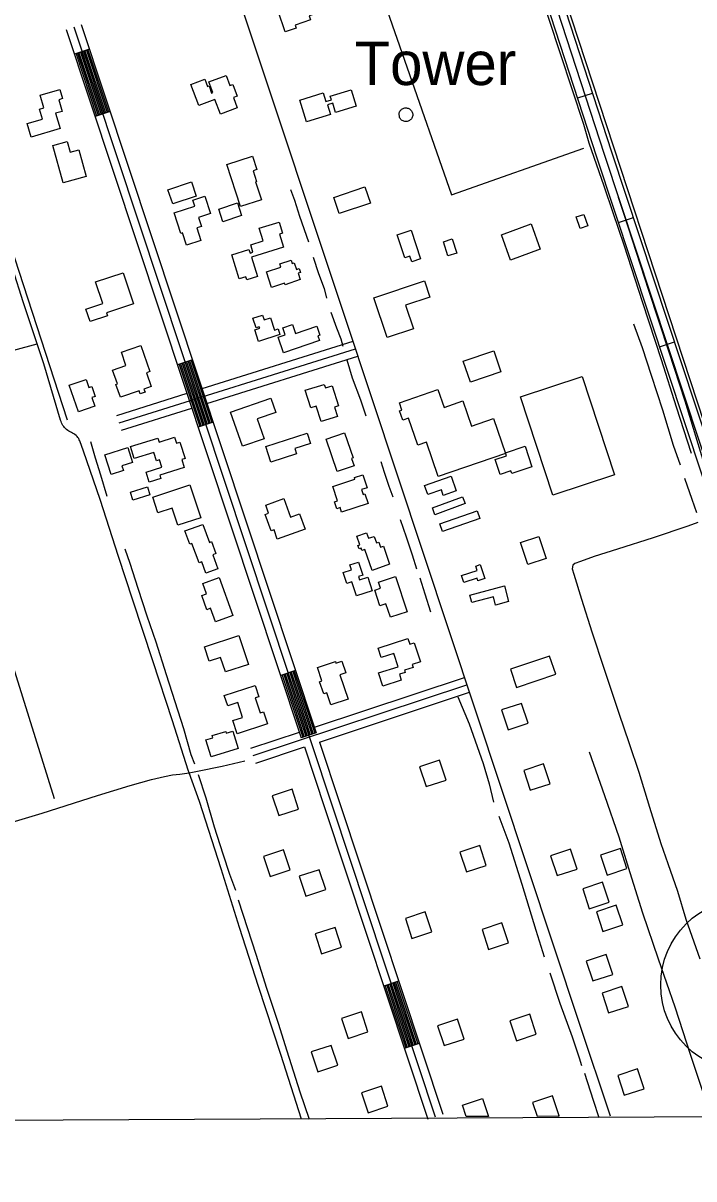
# Model space of a CAD drawing. Extents: x 3445503 to 3483459, y 540493 to 566012.
# Drawn here: x 3471547 to 3472827, y 545885 to 548092 of the extents above; entities that cross this region are included whole.
import ezdxf

# ---------------------------------------------------------------- set-up
doc = ezdxf.new("R2010")
doc.units = 0
for name, color, linetype in [('V-BLDG-OTLN', 7, 'Continuous'), ('V-DOMW-IDEN', 7, 'Continuous'), ('V-DOMW-TANK', 7, 'Continuous'), ('V-DTCH-CNTR', 7, 'Continuous'), ('V-GRID-FRAM', 7, 'Continuous'), ('V-ROAD-CNTR', 7, 'Continuous'), ('V-ROAD-IDEN', 7, 'Continuous'), ('V-TOPO-SHOR', 7, 'Continuous')]:
    doc.layers.add(name, color=color, linetype=linetype)

msp = doc.modelspace()

# ---------------------------------------------------------------- linework, layer by layer
at = {"layer": 'V-BLDG-OTLN'}
for p, q in [((3472434.9, 546004.5), (3472392.8, 546004.2)), ((3472528.1, 546004.9), (3472569.9, 546005.8)), ((3472569.9, 546005.8), (3472567.8, 546005.1))]:
    msp.add_line(p, q, dxfattribs=at)
for points in [[(3472033.6, 548115.4), (3472083, 548132.1), (3472085.1, 548125.8), (3472102.5, 548131.7), (3472109.3, 548111.7), (3472092.7, 548106.1), (3472095.3, 548098.3), (3472066.1, 548088.4), (3472067.9, 548082.9), (3472046.9, 548075.8)], [(3471923.6, 547918.7), (3471913.3, 547946.5), (3471882.3, 547935), (3471867.5, 547975.2), (3471894.2, 547985.1), (3471899.3, 547971.3), (3471901.9, 547972.3), (3471906.9, 547958.8), (3471909, 547959.6), (3471901.4, 547980.1), (3471934.7, 547992.5), (3471941.8, 547973.4), (3471947.2, 547975.4), (3471955.5, 547952.8), (3471948.5, 547950.2), (3471955.8, 547930.6)], [(3471579.6, 547954.7), (3471617.5, 547965.8), (3471622.6, 547948.2), (3471615.1, 547945.9), (3471621.6, 547923.8), (3471609.1, 547920.1), (3471617.7, 547890.8), (3471562.3, 547874.5), (3471554.7, 547900.3), (3471584.3, 547909), (3471578.6, 547928.2), (3471586.7, 547930.6)], [(3472075.2, 547945.4), (3472120, 547959), (3472124.8, 547942.9), (3472135.3, 547946.1), (3472133.3, 547952.9), (3472173.3, 547964.9), (3472182.7, 547933.9), (3472143.2, 547921.9), (3472137.9, 547939.4), (3472128, 547936.4), (3472133.6, 547917.6), (3472087.7, 547903.7)], [(3471623.5, 547787), (3471603.6, 547858.9), (3471631.2, 547866.5), (3471636.9, 547846), (3471653.5, 547850.6), (3471667.7, 547799.3)], [(3471961.7, 547741.9), (3471935.7, 547822.1), (3471984.8, 547838), (3471993, 547812.6), (3471986.1, 547810.4), (3471992.8, 547789.6), (3471990.7, 547788.9), (3472001.8, 547754.8)], [(3471823.6, 547773.7), (3471868.4, 547788.9), (3471877.5, 547762.1), (3471832.7, 547746.9)], [(3472209.8, 547748.5), (3472150.4, 547728.5), (3472140, 547759.4), (3472199.4, 547779.4)], [(3471835.5, 547729.8), (3471875.1, 547742.7), (3471871.3, 547754.5), (3471893.7, 547761.8), (3471904.5, 547728.7), (3471881.9, 547721.3), (3471887.5, 547704.2), (3471878.6, 547701.3), (3471886.5, 547677.2), (3471859.1, 547668.3), (3471851.6, 547691.6), (3471848.3, 547690.5)], [(3471920.4, 547736.9), (3471956.2, 547748.8), (3471964.1, 547725), (3471928.4, 547713.1)], [(3472617.1, 547727.1), (3472624.5, 547705.1), (3472609.8, 547700.3), (3472602.5, 547722.2)], [(3472044.2, 547664.4), (3471983.2, 547645.6), (3471994.7, 547608.3), (3471974, 547601.9), (3471972.1, 547608), (3471959.4, 547604), (3471945.3, 547649.6), (3471978.1, 547659.8), (3471980.2, 547653.1), (3471985.8, 547654.9), (3471981.5, 547669), (3472005.2, 547676.3), (3471997.7, 547700.6), (3472035.7, 547712.3), (3472042.3, 547691), (3472036.5, 547689.2)], [(3472459.7, 547688.1), (3472516.4, 547708.7), (3472534, 547660.4), (3472477.3, 547639.8)], [(3472287.5, 547696.9), (3472305.7, 547641.9), (3472288.7, 547636.3), (3472285.1, 547647.1), (3472275.2, 547643.8), (3472260.6, 547688)], [(3472366.1, 547680.2), (3472374.6, 547653.2), (3472357.6, 547647.8), (3472349, 547674.7)], [(3472011.4, 547617.1), (3472039.1, 547626.1), (3472037, 547632.7), (3472058.6, 547639.8), (3472060.7, 547633.3), (3472064.6, 547634.5), (3472068.8, 547621.8), (3472074.1, 547623.6), (3472076.6, 547616), (3472072.2, 547614.5), (3472076.1, 547602.4), (3472046.9, 547592.8), (3472046, 547595.4), (3472021.1, 547587.2)], [(3471738.1, 547615.6), (3471757.9, 547556.3), (3471706.5, 547539.2), (3471708.4, 547533.4), (3471674.9, 547522.3), (3471667, 547546.2), (3471699.2, 547557), (3471685.6, 547598.1)], [(3472216.3, 547567.9), (3472312.8, 547600.3), (3472323.3, 547569.1), (3472276.8, 547553.5), (3472291.9, 547508.6), (3472241.9, 547491.8)], [(3472019.3, 547529.6), (3472026.8, 547505.9), (3472033.9, 547508.2), (3472037.2, 547497.7), (3471996.3, 547484.6), (3471989.3, 547506.7), (3471998.6, 547509.7), (3471997.7, 547512.6), (3471991.7, 547510.7), (3471985.8, 547529.1), (3472004, 547534.9), (3472007, 547525.6)], [(3472044.2, 547462.4), (3472033.8, 547492.7), (3472047.1, 547497.2), (3472042.5, 547510.5), (3472061.2, 547516.9), (3472067.1, 547499.9), (3472107.5, 547513.8), (3472113.6, 547496.4), (3472109.7, 547495), (3472112.8, 547486)], [(3471771.6, 547476.8), (3471788.9, 547426.8), (3471782.6, 547424.6), (3471791.7, 547398.2), (3471777.8, 547393.4), (3471779.9, 547387.3), (3471770.5, 547384.1), (3471768.5, 547390.1), (3471732.7, 547377.8), (3471724.3, 547402.2), (3471727, 547403.2), (3471717.8, 547429.8), (3471743.4, 547438.7), (3471734.6, 547464)], [(3472387.1, 547446.7), (3472445.1, 547466.4), (3472458.6, 547426.6), (3472400.6, 547406.9)], [(3472613.8, 547417.4), (3472675.7, 547229.7), (3472558, 547190.9), (3472496.1, 547378.6)], [(3471652.6, 547349.9), (3471635.1, 547401), (3471667.2, 547412), (3471672.4, 547396.7), (3471678.2, 547398.7), (3471684.7, 547379.5), (3471678.5, 547377.4), (3471684.2, 547360.7)], [(3472115.8, 547331.5), (3472106.5, 547361.1), (3472095.9, 547357.8), (3472085.4, 547391.1), (3472121.9, 547402.5), (3472124, 547395.7), (3472137.1, 547399.8), (3472149.2, 547361.4), (3472141.5, 547359), (3472147.1, 547341.3)], [(3471965.6, 547284.4), (3471943, 547349.5), (3472019.8, 547376.1), (3472029.2, 547348.9), (3471993.7, 547336.6), (3472006.8, 547298.7)], [(3472265.1, 547367.5), (3472338.5, 547392.9), (3472350.4, 547358.4), (3472386, 547370.7), (3472402.6, 547322.6), (3472444.7, 547337.2), (3472467.7, 547270.7), (3472339.4, 547226.4), (3472316.8, 547292), (3472300.4, 547286.3), (3472282.6, 547337.8), (3472271.6, 547334), (3472265.4, 547352), (3472270, 547353.5)], [(3472010, 547283.8), (3472089.3, 547309.3), (3472095.7, 547289.6), (3472065.7, 547280), (3472069, 547269.5), (3472019.6, 547253.7)], [(3472146.6, 547235.9), (3472125.6, 547298), (3472160.7, 547309.9), (3472176.9, 547261.9), (3472173.8, 547260.9), (3472178.6, 547246.7)], [(3471854.7, 547243.4), (3471808, 547228.8), (3471809.9, 547222.8), (3471788, 547215.9), (3471782.1, 547235), (3471811.9, 547244.3), (3471807.5, 547258.2), (3471801.5, 547256.3), (3471796.4, 547272.6), (3471759.2, 547260.9), (3471752.2, 547283.5), (3471804.1, 547299.8), (3471806.5, 547292.3), (3471836.2, 547301.6), (3471839.8, 547290.2), (3471846.4, 547292.3), (3471856.2, 547260.9), (3471849.9, 547258.9)], [(3472517.8, 547244.7), (3472479.4, 547232.1), (3472477.7, 547237.1), (3472457.4, 547230.4), (3472448.1, 547258.7), (3472469.7, 547265.9), (3472467.6, 547272), (3472504.8, 547284.2)], [(3471703.3, 547267.7), (3471747, 547281.8), (3471756.2, 547253.4), (3471735.6, 547246.8), (3471738.5, 547238), (3471715.4, 547230.5)], [(3472205.5, 547175), (3472154.9, 547158.3), (3472152.1, 547167.1), (3472145.9, 547165), (3472141.6, 547178), (3472147.3, 547179.9), (3472138.2, 547207.3), (3472180.3, 547221.2), (3472179.2, 547224.3), (3472195.6, 547229.7), (3472203.8, 547205.1), (3472192.9, 547201.5), (3472196.1, 547192), (3472199.5, 547193.2)], [(3472313.1, 547209.4), (3472364.2, 547226.9), (3472373.7, 547199), (3472348.9, 547190.5), (3472345.3, 547200.9), (3472319.1, 547191.9)], [(3471789.1, 547191.4), (3471756.7, 547181.3), (3471752, 547196.4), (3471784.4, 547206.5)], [(3471794.4, 547187.2), (3471865.6, 547210.7), (3471886.3, 547147.9), (3471842.4, 547133.4), (3471831.6, 547166), (3471804.4, 547157)], [(3472044.7, 547184.3), (3472057.5, 547149.1), (3472074.5, 547155.3), (3472085.1, 547126.2), (3472032.2, 547107.1), (3472025.9, 547124.6), (3472020.6, 547122.6), (3472009.3, 547154), (3472015.7, 547156.3), (3472010.1, 547171.8)], [(3472328.1, 547166.5), (3472385.6, 547187.8), (3472390.4, 547174.9), (3472332.9, 547153.6)], [(3472342.1, 547135.9), (3472413.4, 547160.9), (3472418.6, 547146.2), (3472347.2, 547121.2)], [(3471890.1, 547134.8), (3471902.6, 547100.5), (3471906.9, 547102.1), (3471915.2, 547079.3), (3471909.3, 547077.1), (3471919, 547050.5), (3471895.7, 547042.1), (3471888, 547063.3), (3471882.8, 547061.4), (3471869.3, 547098.6), (3471865.2, 547097.1), (3471856, 547122.5)], [(3472212.9, 547047.3), (3472199.2, 547086.9), (3472193.6, 547085), (3472192.1, 547089.4), (3472188.4, 547088.1), (3472186.1, 547094.8), (3472189.4, 547095.9), (3472183.7, 547112.3), (3472202.5, 547118.8), (3472206.1, 547108.5), (3472217, 547112.2), (3472221.3, 547099.8), (3472225.7, 547101.3), (3472229.1, 547091.6), (3472234.5, 547093.4), (3472246.5, 547058.9)], [(3472531.2, 547112), (3472545.2, 547070.1), (3472509.9, 547058.3), (3472495.9, 547100.2)], [(3472213.2, 547008.3), (3472183.5, 546998.5), (3472174.6, 547025.3), (3472164.7, 547022), (3472157.6, 547043.2), (3472173.9, 547048.6), (3472170.8, 547057.8), (3472187.3, 547063.2), (3472195.5, 547038.4), (3472186.9, 547035.5), (3472189, 547029.1), (3472204.6, 547034.3)], [(3472383.8, 547037.3), (3472413.6, 547047.3), (3472410.8, 547055.6), (3472419.3, 547058.5), (3472428.2, 547031.7), (3472415, 547027.3), (3472413.3, 547032.4), (3472388.3, 547024)], [(3471921.5, 547033.5), (3471947.5, 546961.2), (3471914.1, 546949.2), (3471904.9, 546974.8), (3471897.9, 546972.2), (3471888.3, 546999.1), (3471896.9, 547002.2), (3471889.8, 547022.1)], [(3472257.5, 547035.3), (3472279.8, 546968.2), (3472248.1, 546957.7), (3472239.5, 546983.5), (3472227.9, 546979.7), (3472218, 547009.6), (3472228.9, 547013.2), (3472225.2, 547024.5)], [(3472399.6, 546999.7), (3472465.4, 547017.8), (3472473.6, 546987.9), (3472448.8, 546981), (3472444.4, 546997), (3472403.4, 546985.7)], [(3471893.4, 546901.3), (3471959, 546923), (3471977.3, 546867.8), (3471933.2, 546853.2), (3471923.9, 546881.2), (3471902.4, 546874.1)], [(3472225.5, 546851.4), (3472262.6, 546863.2), (3472254.5, 546888.7), (3472230.1, 546880.9), (3472224.4, 546898.9), (3472281.3, 546917.1), (3472284.8, 546906.4), (3472293.5, 546909.2), (3472305.3, 546872.5), (3472289.5, 546867.4), (3472291.2, 546862), (3472274.8, 546856.8), (3472276.2, 546852.5), (3472265.1, 546849), (3472268.8, 546837.4), (3472233.6, 546826.1)], [(3472151.3, 546847.8), (3472167.1, 546801.6), (3472134.3, 546790.5), (3472126.5, 546813.3), (3472120.8, 546811.3), (3472112.8, 546834.6), (3472117.3, 546836.2), (3472108.7, 546861.5), (3472143, 546873.2), (3472144.1, 546869.9), (3472155.2, 546873.7), (3472162.7, 546851.7)], [(3472476.9, 546858.3), (3472488.5, 546823.7), (3472563.4, 546848.9), (3472551.8, 546883.4)], [(3471931, 546808.5), (3471989.8, 546827.7), (3471996.9, 546806), (3471989.9, 546803.7), (3471999.3, 546775), (3472005.8, 546777.1), (3472013.3, 546754.2), (3471955.3, 546735.2), (3471947.1, 546760.3), (3471965.9, 546766.4), (3471956.6, 546794.7), (3471937.6, 546788.5)], [(3472460.1, 546780.7), (3472472.7, 546742.7), (3472510.6, 546755.3), (3472498.1, 546793.3)], [(3471957.6, 546706.8), (3471906, 546691.2), (3471896.1, 546723.8), (3471909.1, 546727.7), (3471907.8, 546731.7), (3471933.9, 546739.6), (3471934.8, 546736.6), (3471947.4, 546740.4)], [(3472303.8, 546672.4), (3472316.3, 546634.4), (3472354.3, 546646.9), (3472341.7, 546684.9)], [(3472502.4, 546665.3), (3472514.9, 546627.3), (3472552.9, 546639.9), (3472540.3, 546677.8)], [(3472072.9, 546591.5), (3472060.5, 546629.5), (3472022.5, 546617), (3472034.9, 546579)], [(3472056.5, 546475.3), (3472044, 546513.3), (3472006, 546500.8), (3472018.5, 546462.8)], [(3472380.5, 546509.4), (3472393, 546471.4), (3472431, 546483.9), (3472418.5, 546521.9)], [(3472553.6, 546502.2), (3472566.1, 546464.3), (3472604.1, 546476.8), (3472591.5, 546514.8)], [(3472648.7, 546503.4), (3472661.3, 546465.5), (3472699.3, 546478), (3472686.7, 546516)], [(3472124.5, 546437.7), (3472112, 546475.7), (3472074, 546463.3), (3472086.5, 546425.2)], [(3472615, 546439.1), (3472627.5, 546401.1), (3472665.5, 546413.6), (3472652.9, 546451.6)], [(3472641, 546395.5), (3472653.6, 546357.5), (3472691.6, 546370.1), (3472679, 546408)], [(3472276.6, 546382.6), (3472289.1, 546344.6), (3472327.1, 546357.1), (3472314.6, 546395.1)], [(3472154.7, 546327.6), (3472142.3, 546365.6), (3472104.3, 546353.2), (3472116.7, 546315.1)], [(3472422.9, 546361.5), (3472435.4, 546323.5), (3472473.4, 546336.1), (3472460.9, 546374)], [(3472621.7, 546301.2), (3472634.2, 546263.3), (3472672.2, 546275.8), (3472659.7, 546313.8)], [(3472651.8, 546240.1), (3472664.3, 546202.1), (3472702.3, 546214.6), (3472689.8, 546252.6)], [(3472205.2, 546166), (3472192.7, 546204), (3472154.7, 546191.5), (3472167.2, 546153.5)], [(3472338.1, 546177.7), (3472350.6, 546139.7), (3472388.6, 546152.2), (3472376.1, 546190.2)], [(3472475.9, 546187), (3472488.4, 546149), (3472526.4, 546161.6), (3472513.9, 546199.6)], [(3472147.5, 546102.1), (3472135.1, 546140.1), (3472097.1, 546127.6), (3472109.5, 546089.6)], [(3472681.7, 546082.9), (3472694.2, 546045), (3472732.2, 546057.5), (3472719.7, 546095.5)], [(3472243.3, 546024), (3472230.8, 546062), (3472192.8, 546049.6), (3472205.3, 546011.6)]]:
    msp.add_lwpolyline(points, close=True, dxfattribs=at)
for points in [[(3472385.6, 546026.3), (3472423.5, 546038.8), (3472434.9, 546004.5)], [(3472392.8, 546004.2), (3472385.6, 546026.3)], [(3472567.8, 546005.1), (3472569.9, 546005.8), (3472557.3, 546043.8), (3472519.4, 546031.3)], [(3472519.4, 546031.3), (3472528.1, 546004.9)]]:
    msp.add_lwpolyline(points, dxfattribs=at)
at = {"layer": 'V-DOMW-TANK'}
msp.add_lwpolyline([(3472264.6, 547919.4), (3472264.9, 547921), (3472265.5, 547922.5), (3472266.2, 547924), (3472267.1, 547925.3), (3472268.2, 547926.6), (3472269.4, 547927.7), (3472270.8, 547928.6), (3472272.2, 547929.4), (3472273.7, 547929.9), (3472275.3, 547930.3), (3472277, 547930.5), (3472278.6, 547930.5), (3472280.2, 547930.2), (3472281.8, 547929.8), (3472283.3, 547929.2), (3472284.7, 547928.4), (3472286, 547927.4), (3472287.2, 547926.3), (3472288.3, 547925), (3472289.1, 547923.6), (3472289.8, 547922.2), (3472290.3, 547920.6), (3472290.6, 547919), (3472290.7, 547917.4), (3472290.6, 547915.7), (3472290.3, 547914.1), (3472289.7, 547912.6), (3472289, 547911.1), (3472288.2, 547909.7), (3472287.1, 547908.5), (3472285.9, 547907.3), (3472284.6, 547906.4), (3472283.2, 547905.6), (3472281.6, 547905), (3472280.1, 547904.6), (3472278.4, 547904.4), (3472276.8, 547904.3), (3472275.2, 547904.5), (3472273.6, 547904.9), (3472272.1, 547905.5), (3472270.6, 547906.3), (3472269.3, 547907.2), (3472268.1, 547908.3), (3472267, 547909.6), (3472266.1, 547910.9), (3472265.4, 547912.4)], close=True, dxfattribs=at)
at = {"layer": 'V-DTCH-CNTR'}
msp.add_line((3471630.2, 547316.1), (3471628.2, 547317.9), dxfattribs=at)
for points in [[(3471628.2, 547317.9), (3471626.3, 547319.9), (3471624.6, 547322), (3471623.1, 547324.2), (3471621.8, 547326.5), (3471620.6, 547328.9), (3471619.6, 547331.4), (3471618.8, 547334), (3471586.5, 547441.8), (3471574, 547479.7), (3471547.4, 547560.3), (3471508.1, 547684.8), (3471465, 547816.1), (3471438.8, 547899.3)], [(3473067.9, 546587.2), (3473044.6, 546656.6), (3473012.2, 546750.7), (3472979.6, 546850.5), (3472948.7, 546947.7), (3472915.5, 547055.2), (3472878.2, 547167.9), (3472846.5, 547251.6), (3472810.3, 547370.2), (3472779.9, 547464), (3472740.9, 547581.7), (3472693.8, 547726.8), (3472683.5, 547759.5)], [(3470702.9, 547215.5), (3470781, 547238.4), (3470871.9, 547265.9), (3470954.5, 547291.9), (3471056.1, 547323.9), (3471169.6, 547361), (3471226.1, 547378.8), (3471256, 547388.2), (3471341, 547412.5), (3471436.7, 547439), (3471529.2, 547467.6), (3471574, 547479.7)], [(3472078.4, 545999.4), (3472038.7, 546122.9), (3471996.3, 546252.6), (3471960.1, 546365.6), (3471924.9, 546477.1), (3471883.8, 546605.8), (3471864.3, 546660.8), (3471862.4, 546666), (3471832, 546759.8), (3471794.7, 546874.6), (3471756.6, 546990.1), (3471729.4, 547073.7), (3471694.3, 547182.5), (3471662.4, 547275.2), (3471655.5, 547294.4), (3471654.4, 547296.7), (3471653.2, 547299), (3471651.7, 547301.2), (3471650, 547303.2), (3471648.1, 547305), (3471646.1, 547306.7), (3471644, 547308.1), (3471641.7, 547309.4), (3471639.3, 547310.4), (3471636.9, 547311.6), (3471634.5, 547312.9), (3471632.3, 547314.4), (3471630.2, 547316.1)], [(3470981.6, 546413.7), (3471065.8, 546436.4), (3471163.6, 546462.8), (3471275.7, 546494.2), (3471389.2, 546527.2), (3471462.4, 546547.6), (3471479.1, 546552.2), (3471583.5, 546583.8), (3471688.8, 546617.4), (3471751.3, 546636.6), (3471792, 546648.2), (3471817, 546653.7), (3471832.2, 546656.6), (3471846.1, 546658.3), (3471864.3, 546660.8), (3471879.9, 546664.1), (3471927, 546673.4), (3471970.5, 546683.4)]]:
    msp.add_lwpolyline(points, dxfattribs=at)
at = {"layer": 'V-GRID-FRAM'}
msp.add_lwpolyline([(3449565.1, 564068.2), (3481202, 564229.3), (3481302.5, 546046.4), (3449649.7, 545885.3), (3449565.1, 564068.2)], dxfattribs=at)
at = {"layer": 'V-ROAD-CNTR'}
for p, q in [((3471673.8, 548042.3), (3471645.3, 548032.9)), ((3472605.3, 547949.4), (3472633.8, 547958.6)), ((3471713.1, 547923.7), (3471684.6, 547914.2)), ((3472683.2, 547711.8), (3472711.7, 547721.2)), ((3472761.7, 547474.4), (3472790.2, 547483.8)), ((3471870.5, 547449.1), (3471842, 547439.6)), ((3471909.8, 547330.4), (3471881.3, 547321)), ((3472067.2, 546855.8), (3472038.7, 546846.4)), ((3472106.5, 546737.2), (3472078, 546727.7)), ((3472263.7, 546262.5), (3472235.2, 546253.1)), ((3472303, 546143.9), (3472274.5, 546134.4))]:
    msp.add_line(p, q, dxfattribs=at)
for points in [[(3473246.5, 546008.6), (3472642, 547836.5), (3472283.2, 548940.1)], [(3473262.3, 546008.7), (3472656.2, 547841.2), (3472297.5, 548944.7)], [(3473044.7, 546714.3), (3472670.5, 547845.9), (3472311.7, 548949.4)], [(3471782.6, 548668.8), (3472161.9, 547528.9), (3472608, 546182.7), (3472667.2, 546005.6)], [(3471629.6, 548080.3), (3472078, 546727.7)], [(3471643.8, 548085), (3472137, 546597.5), (3472333.5, 546003.9)], [(3471658, 548089.8), (3472106.5, 546737.2)], [(3471648.1, 548033.8), (3471687.5, 547915.2)], [(3471651, 548034.8), (3471690.3, 547916.1)], [(3471653.8, 548035.7), (3471693.2, 547917)], [(3471656.7, 548036.6), (3471696, 547918)], [(3471659.5, 548037.6), (3471698.9, 547918.9)], [(3471662.4, 548038.5), (3471701.7, 547919.9)], [(3471665.2, 548039.5), (3471704.6, 547920.8)], [(3471668.1, 548040.4), (3471707.4, 547921.8)], [(3471670.9, 548041.4), (3471710.3, 547922.7)], [(3471888.6, 547394.4), (3472176.7, 547484.9)], [(3471730.3, 547329), (3472181.2, 547470.6)], [(3471844.8, 547440.6), (3471884.2, 547321.9)], [(3471847.7, 547441.5), (3471887, 547322.9)], [(3471850.5, 547442.5), (3471889.9, 547323.8)], [(3471853.4, 547443.4), (3471892.7, 547324.8)], [(3471856.2, 547444.3), (3471895.6, 547325.7)], [(3471859.1, 547445.3), (3471898.4, 547326.6)], [(3471861.9, 547446.2), (3471901.3, 547327.6)], [(3471864.8, 547447.2), (3471904.1, 547328.5)], [(3471867.6, 547448.1), (3471907, 547329.5)], [(3471898, 547366), (3472185.7, 547456.3)], [(3471725.8, 547343.3), (3471860, 547385.5)], [(3471734.8, 547314.7), (3471869.4, 547357)], [(3472041.5, 546847.3), (3472080.9, 546728.7)], [(3472044.4, 546848.3), (3472083.7, 546729.6)], [(3472047.2, 546849.2), (3472086.6, 546730.6)], [(3472050.1, 546850.2), (3472089.4, 546731.5)], [(3472052.9, 546851.1), (3472092.3, 546732.5)], [(3472055.8, 546852.1), (3472095.1, 546733.4)], [(3472058.6, 546853), (3472098, 546734.3)], [(3472061.5, 546853.9), (3472100.8, 546735.3)], [(3472064.3, 546854.9), (3472103.7, 546736.2)], [(3472102.9, 546747.9), (3472389.2, 546842.9)], [(3471986.4, 546693.5), (3472393.9, 546828.7)], [(3472112.4, 546719.4), (3472398.6, 546814.4)], [(3471981.7, 546707.7), (3472074.5, 546738.5)], [(3471991.2, 546679.2), (3472083.9, 546710)], [(3472083.9, 546710), (3472122.8, 546592.8), (3472319.2, 545999.2)], [(3472112.4, 546719.4), (3472151.3, 546602.2), (3472347.7, 546008.7)], [(3472238.1, 546254), (3472277.3, 546135.4)], [(3472240.9, 546255), (3472280.2, 546136.3)], [(3472243.8, 546255.9), (3472283, 546137.3)], [(3472246.6, 546256.9), (3472285.9, 546138.2)], [(3472249.5, 546257.8), (3472288.7, 546139.1)], [(3472252.3, 546258.8), (3472291.6, 546140.1)], [(3472255.1, 546259.7), (3472294.4, 546141)], [(3472258, 546260.6), (3472297.3, 546142)], [(3472260.8, 546261.6), (3472300.1, 546142.9)]]:
    msp.add_lwpolyline(points, dxfattribs=at)
at = {"layer": 'V-ROAD-IDEN'}
msp.add_circle((3472928.8, 546255.5), 165, dxfattribs=at)
msp.add_circle((3472928.8, 546255.5), 165, dxfattribs=at)
at = {"layer": 'V-TOPO-SHOR'}
for p, q in [((3472567.3, 548180.1), (3472859.3, 547289.3)), ((3471631.9, 547333.9), (3471364.7, 548155.4)), ((3471607.2, 546611.3), (3471359.7, 547403.2))]:
    msp.add_line(p, q, dxfattribs=at)
for points in [[(3472290.9, 548907), (3472315.5, 548830.7), (3472370.4, 548646.9), (3472423.5, 548486.3), (3472494.9, 548264.6), (3472549.7, 548101.7), (3472616.3, 547899.4), (3472626.6, 547863.9), (3472655.2, 547781.3)], [(3472185.2, 548279.2), (3472364.4, 547764.4), (3472616.8, 547853.5)], [(3472057.4, 547774.4), (3472065.3, 547754.1), (3472074.5, 547723.7), (3472091.6, 547674.6)], [(3472655.2, 547781.3), (3472672.2, 547730.6), (3472693.1, 547668.9), (3472728.9, 547558.6), (3472764.5, 547450), (3472793.4, 547359.7), (3472821.9, 547271.2)], [(3472100.3, 547645.4), (3472110.9, 547614.4), (3472121.3, 547585.6), (3472126.1, 547567.1)], [(3472134, 547540.3), (3472145.3, 547510.6), (3472153.5, 547489.3), (3472157.2, 547475.2)], [(3472712.1, 547517.9), (3472728.5, 547472.8), (3472745.4, 547420.2), (3472767.4, 547354), (3472787.7, 547286.5), (3472800.7, 547249.1)], [(3472164.7, 547449.6), (3472175.2, 547415.2), (3472190.8, 547372.9), (3472200.8, 547342.5)], [(3471675.8, 547293.5), (3471684.6, 547262.1), (3471695.1, 547229.6), (3471707, 547189.1)], [(3472229.6, 547255.1), (3472236, 547234.9), (3472244.8, 547207.9), (3472252.4, 547187.9)], [(3472809, 547223.2), (3472823.3, 547183.1), (3472832, 547157.6)], [(3472266.4, 547144.7), (3472278.2, 547111.4), (3472289.2, 547077.2), (3472297.9, 547050.3)], [(3472834.5, 547138.5), (3472815.6, 547131.4), (3472749.5, 547109.6), (3472681.5, 547087.9), (3472636.5, 547073.7), (3472610.8, 547064.5), (3472599.6, 547060.6), (3472596.3, 547057.2), (3472595.1, 547050.1), (3472598, 547040.1), (3472612.6, 546992.1), (3472632, 546930), (3472655.9, 546858.5), (3472683.6, 546774.6), (3472703.6, 546716.7), (3472721.8, 546662.2), (3472742.5, 546595.2), (3472764.2, 546525.9), (3472777.3, 546487.8), (3472795.5, 546434.5), (3472811.6, 546381.4), (3472838.1, 546305.4)], [(3471741.1, 547088.3), (3471750.9, 547060.8), (3471766.1, 547013.5), (3471783.3, 546960.5), (3471800.1, 546911.1), (3471820.2, 546848.5), (3471836.8, 546796.8), (3471853.2, 546745.4), (3471867.4, 546695.4), (3471873.9, 546677.8)], [(3472304, 547033), (3472313.9, 547002.5), (3472324.8, 546967.9)], [(3472376.6, 546805.5), (3472398.1, 546754), (3472424.9, 546678.2), (3472436.5, 546639.8), (3472444.6, 546604.4)], [(3472860.2, 546003.4), (3472852.3, 546027.1), (3472821.1, 546121.1), (3472791.2, 546213.3), (3472759.2, 546304.6), (3472729.9, 546392.4), (3472705.6, 546469.4), (3472684.5, 546537.6), (3472657, 546616.6), (3472628, 546700.2)], [(3471880.9, 546657.2), (3471895.5, 546612.9), (3471912, 546557.7), (3471928.3, 546505.9), (3471941.1, 546467.4), (3471952.6, 546436.8)], [(3472454.6, 546578), (3472474.1, 546527.2), (3472498.5, 546447.8), (3472525.7, 546360), (3472541.3, 546309.3)], [(3471957.6, 546418), (3471975.6, 546363.7), (3471991.1, 546314.1), (3472011.7, 546249.7), (3472033.7, 546182.6), (3472050.5, 546130), (3472075.3, 546051.8), (3472093, 545999.5)], [(3472551.9, 546278.8), (3472571, 546220.9), (3472595.1, 546156.4), (3472607.9, 546116.7), (3472612.3, 546102)], [(3472618.1, 546087.1), (3472634.6, 546035.5), (3472645.8, 546002.3)]]:
    msp.add_lwpolyline(points, dxfattribs=at)

# ---------------------------------------------------------------- texts
at = {"layer": 'V-DOMW-IDEN'}
msp.add_text(' Tower', height=83, dxfattribs=at).set_placement((3472148.7, 547974))

doc.saveas('drawing.dxf')
